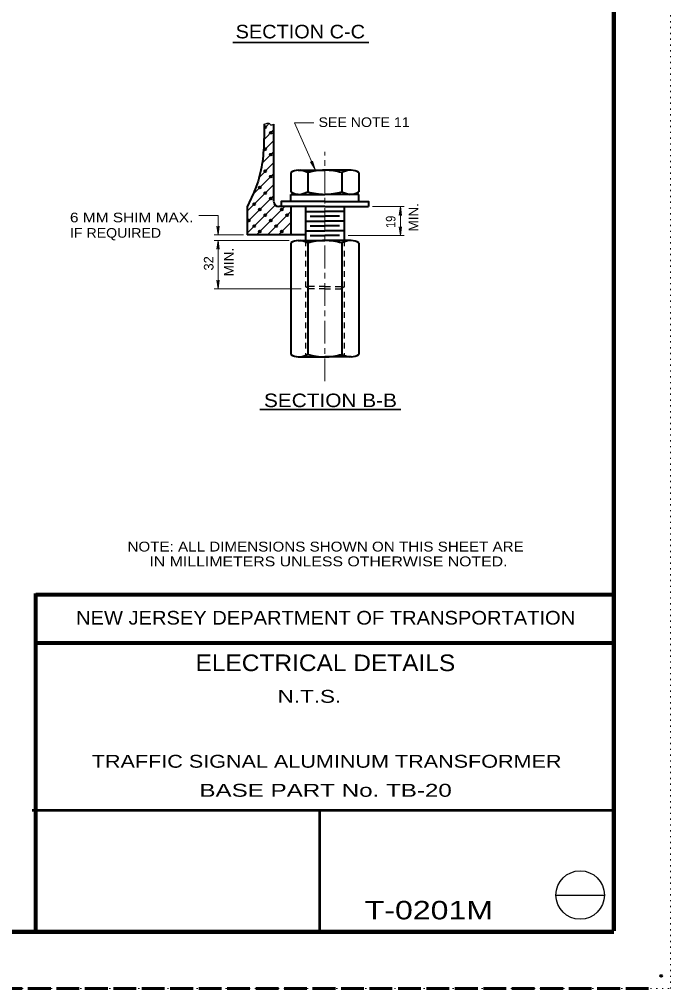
# Model space of a CAD drawing. Extents: x 312583 to 312854, y 144419 to 144597.
# Drawn here: x 312802 to 312853.5, y 144418.6 to 144495.2 of the extents above; entities that cross this region are included whole.
import ezdxf
from ezdxf.enums import TextEntityAlignment as Align

# ---------------------------------------------------------------- set-up
doc = ezdxf.new("R2010")
doc.units = 0
doc.header["$LTSCALE"] = 0.3
doc.header["$PDMODE"] = 32
doc.header["$PDSIZE"] = 0.15
for name, pattern in [('DOTTED', [1.5, 0.3, -1.2]), ('LONG_DASH_SHORT_DASH', [9.9, 6, -1.2, 1.5, -1.2]), ('LONG_DASHED', [7.5, 6, -1.5]), ('SHORT_DASHED', [2.7, 1.5, -1.2])]:
    doc.linetypes.add(name, pattern=pattern)
for name, color, linetype, lineweight in [('1', 7, 'Continuous', 40), ('2', 7, 'Continuous', 13), ('62', 7, 'DOTTED', 13), ('63', 7, 'LONG_DASHED', 60)]:
    doc.layers.add(name, color=color, linetype=linetype, lineweight=lineweight)
doc.layers.add('5', color=7, linetype='Continuous')

msp = doc.modelspace()

# ---------------------------------------------------------------- linework, layer by layer
at = {"layer": '1', "lineweight": 158}
for p, q in [((312849, 144423.1446), (312849, 144585.0846)), ((312616.5, 144423.0846), (312849, 144423.0846))]:
    msp.add_line(p, q, dxfattribs=at)
at = {"layer": '1', "lineweight": 13}
for p, q in [((312821.3437, 144485.6762), (312822.1411, 144486.4735)), ((312821.3667, 144486.5655), (312821.7117, 144486.9105)), ((312821.2977, 144484.7562), (312822.1411, 144485.5995)), ((312821.1904, 144483.7902), (312822.1411, 144484.7332)), ((312820.9681, 144482.6938), (312822.1411, 144483.8668)), ((312820.5541, 144481.4212), (312822.1411, 144483.0005)), ((312820.0327, 144480.0258), (312822.1411, 144482.1342)), ((312820.0327, 144479.1595), (312822.1411, 144481.2678)), ((312820.0327, 144478.2855), (312822.2254, 144480.4858)), ((312820.7687, 144478.1628), (312822.9997, 144480.3938)), ((312821.6351, 144478.1628), (312823.4827, 144480.0028)), ((312822.5014, 144478.1628), (312823.4827, 144479.1365)), ((312823.3754, 144478.1628), (312823.4827, 144478.2702))]:
    msp.add_line(p, q, dxfattribs=at)
at = {"layer": '1'}
for p, q in [((312822.1411, 144480.7772), (312822.1411, 144486.9105)), ((312823.4827, 144483.0772), (312823.4827, 144481.5438)), ((312824.0654, 144483.2688), (312826.1661, 144483.2688)), ((312824.8244, 144483.0772), (312824.8244, 144481.5438)), ((312828.2591, 144483.2688), (312826.1661, 144483.2688)), ((312827.5001, 144483.0772), (312827.5001, 144481.5438)), ((312828.8494, 144483.0772), (312828.8494, 144481.5438)), ((312823.4827, 144480.7772), (312823.4827, 144481.3522)), ((312823.4827, 144481.3522), (312826.1661, 144481.3522)), ((312828.8494, 144481.3522), (312826.1661, 144481.3522)), ((312828.8494, 144480.7772), (312828.8494, 144481.3522)), ((312820.0327, 144480.3938), (312820.0327, 144478.1628)), ((312822.7161, 144480.3938), (312822.5244, 144480.3938)), ((312826.1661, 144480.3938), (312822.7161, 144480.3938)), ((312823.4827, 144480.3938), (312823.4827, 144478.1628)), ((312824.6327, 144480.3938), (312824.6327, 144477.7105)), ((312826.1661, 144480.3938), (312829.6161, 144480.3938)), ((312827.6994, 144480.3938), (312827.6994, 144477.7105)), ((312824.6327, 144480.0105), (312826.1661, 144480.0105)), ((312825.0161, 144479.6272), (312826.1661, 144479.6272)), ((312827.6994, 144480.0105), (312826.1661, 144480.0105)), ((312827.3161, 144479.6272), (312826.1661, 144479.6272)), ((312824.6327, 144479.2438), (312826.1661, 144479.2438)), ((312825.0161, 144478.8605), (312826.1661, 144478.8605)), ((312827.6994, 144479.2438), (312826.1661, 144479.2438)), ((312827.3161, 144478.8605), (312826.1661, 144478.8605)), ((312824.6327, 144478.1628), (312820.0327, 144478.1628)), ((312824.6327, 144478.4772), (312826.1661, 144478.4772)), ((312825.0161, 144478.0938), (312826.1661, 144478.0938)), ((312827.6994, 144478.4772), (312826.1661, 144478.4772)), ((312827.3161, 144478.0938), (312826.1661, 144478.0938)), ((312823.4827, 144477.5188), (312823.4827, 144468.7022)), ((312824.0654, 144477.7105), (312826.1661, 144477.7105)), ((312824.8244, 144477.5188), (312824.8244, 144468.7022)), ((312828.2591, 144477.7105), (312826.1661, 144477.7105)), ((312827.5001, 144477.5188), (312827.5001, 144468.7022)), ((312828.8494, 144477.5188), (312828.8494, 144468.7022)), ((312824.0654, 144468.5105), (312826.1661, 144468.5105)), ((312828.2591, 144468.5105), (312826.1661, 144468.5105))]:
    msp.add_line(p, q, dxfattribs=at)
at = {"layer": '1', "linetype": 'LONG_DASH_SHORT_DASH', "lineweight": 13}
msp.add_line((312826.1661, 144466.5938), (312826.1661, 144484.7255), dxfattribs=at)
at = {"layer": '1', "linetype": 'SHORT_DASHED', "lineweight": 25}
for p, q in [((312824.6327, 144477.7105), (312824.6327, 144468.5105)), ((312827.6994, 144477.7105), (312827.6994, 144468.5105)), ((312826.1661, 144474.0688), (312824.6327, 144474.0688)), ((312824.9087, 144473.8772), (312824.6327, 144474.0688)), ((312826.1661, 144473.8772), (312824.9087, 144473.8772)), ((312826.1661, 144474.0688), (312827.6994, 144474.0688)), ((312826.1661, 144473.8772), (312827.4234, 144473.8772)), ((312827.4234, 144473.8772), (312827.6994, 144474.0688))]:
    msp.add_line(p, q, dxfattribs=at)
at = {"layer": '1', "lineweight": 80}
for p, q in [((312803.31, 144423.1446), (312803.31, 144449.8146)), ((312803.31, 144449.7246), (312849, 144449.7246)), ((312803.31, 144445.9146), (312849, 144445.9146))]:
    msp.add_line(p, q, dxfattribs=at)
at = {"layer": '1', "lineweight": 53}
for p, q in [((312849, 144432.6666), (312803.0383, 144432.6666)), ((312825.7547, 144432.6666), (312825.7547, 144423.1446))]:
    msp.add_line(p, q, dxfattribs=at)
at = {"layer": '1', "lineweight": 25}
msp.add_line((312844.4384, 144425.966), (312848.2794, 144425.966), dxfattribs=at)
at = {"layer": '1'}
for points in [[(312826.1661, 144480.7772), (312822.7161, 144480.7772), (312822.7161, 144480.3938)], [(312826.1661, 144480.7772), (312829.6161, 144480.7772), (312829.6161, 144480.3938)]]:
    msp.add_lwpolyline(points, dxfattribs=at)
at = {"layer": '1', "lineweight": 25}
msp.add_circle((312846.3494, 144425.9805), 1.9159, dxfattribs=at)
at = {"layer": '1'}
for centre, radius, start, end in [((312824.1006, 144482.1596), 1.1066, 91.66257, 124.1297), ((312823.5662, 144480.1666), 3.1689, 66.63635, 78.22986), ((312826.3032, 144477.5516), 5.7189, 91.405, 105.00202), ((312826.0228, 144477.5516), 5.7189, 74.99798, 88.595), ((312828.7598, 144480.1666), 3.1689, 101.77014, 113.36365), ((312828.2254, 144482.1596), 1.1066, 55.8703, 88.33743), ((312824.1006, 144482.4645), 1.1066, 235.8703, 268.33743), ((312823.5662, 144484.4575), 3.1689, 281.77014, 293.36365), ((312826.3032, 144487.0724), 5.7189, 254.99798, 268.595), ((312826.0228, 144487.0724), 5.7189, 271.405, 285.00202), ((312828.7598, 144484.4575), 3.1689, 246.63635, 258.22986), ((312828.2254, 144482.4645), 1.1066, 271.66257, 304.1297), ((312822.5229, 144480.7756), 0.3833, 180, 270), ((312824.1006, 144476.5997), 1.1066, 91.66257, 124.1297), ((312823.5662, 144474.6067), 3.1689, 66.63635, 78.22986), ((312826.3032, 144471.9918), 5.7189, 91.405, 105.00202), ((312826.0228, 144471.9918), 5.7189, 74.99798, 88.595), ((312828.7598, 144474.6067), 3.1689, 101.77014, 113.36365), ((312828.2254, 144476.5997), 1.1066, 55.8703, 88.33743), ((312824.1006, 144469.6182), 1.1066, 235.8703, 268.33743), ((312823.5662, 144471.6112), 3.1689, 281.77014, 293.36365), ((312826.3032, 144474.2262), 5.7189, 254.99798, 268.595), ((312826.0228, 144474.2262), 5.7189, 271.405, 285.00202), ((312828.7598, 144471.6112), 3.1689, 246.63635, 258.22986), ((312828.2254, 144469.6182), 1.1066, 271.66257, 304.1297)]:
    msp.add_arc(centre, radius, start, end, dxfattribs=at)
msp.add_spline([(312821.3744, 144486.9105), (312821.3514, 144485.5152), (312821.1981, 144483.7135), (312820.7381, 144481.9732), (312820.0327, 144480.3938)], degree=3, dxfattribs=at)
for p in [(312821.4587, 144486.6575), (312821.8957, 144486.2282), (312821.4587, 144484.9248), (312821.8957, 144484.4955), (312821.4587, 144483.1922), (312821.8957, 144482.7552), (312821.0294, 144481.8888), (312821.4587, 144481.4595), (312820.5924, 144480.5855), (312821.8957, 144481.0225), (312821.0294, 144480.1562), (312821.4587, 144479.7192), (312822.7621, 144480.1562), (312823.1914, 144479.7192), (312820.1554, 144479.2822), (312820.5924, 144478.8528), (312821.8957, 144479.2822), (312822.3251, 144478.8528), (312821.0294, 144478.4235), (312822.7621, 144478.4235), (312852.75, 144419.5846)]:
    msp.add_point(p, dxfattribs=at)
at = {"layer": '2', "lineweight": 35}
for p, q in [((312818.8934, 144493.3585), (312829.6468, 144493.3585)), ((312821.0371, 144464.3552), (312832.1691, 144464.3552))]:
    msp.add_line(p, q, dxfattribs=at)
at = {"layer": '2'}
for p, q in [((312825.0314, 144483.9205), (312825.2001, 144483.7518)), ((312825.3917, 144483.3148), (312825.0314, 144483.9205)), ((312825.1924, 144483.9895), (312825.2001, 144483.7518)), ((312825.3917, 144483.3148), (312825.1924, 144483.9895)), ((312832.4451, 144480.3938), (312829.9227, 144480.3938)), ((312832.1384, 144480.3938), (312832.0541, 144479.6962)), ((312832.1384, 144478.0938), (312832.1384, 144480.3938)), ((312832.1384, 144480.3938), (312832.2227, 144479.6962)), ((312816.1994, 144479.6962), (312817.7327, 144479.6962)), ((312817.7327, 144478.1628), (312817.7327, 144479.6962)), ((312832.0541, 144479.6962), (312832.1384, 144479.9185)), ((312832.2227, 144479.6962), (312832.1384, 144479.9185)), ((312817.6407, 144478.8528), (312817.7327, 144478.6305)), ((312817.7327, 144478.1628), (312817.6407, 144478.8528)), ((312817.8171, 144478.8528), (312817.7327, 144478.6305)), ((312817.7327, 144478.1628), (312817.8171, 144478.8528)), ((312819.7261, 144478.1628), (312817.4261, 144478.1628)), ((312832.4451, 144478.0938), (312827.9984, 144478.0938)), ((312832.0541, 144478.7838), (312832.1384, 144478.5615)), ((312832.1384, 144478.0938), (312832.0541, 144478.7838)), ((312832.2227, 144478.7838), (312832.1384, 144478.5615)), ((312832.1384, 144478.0938), (312832.2227, 144478.7838)), ((312823.3447, 144477.7105), (312817.4261, 144477.7105)), ((312817.7327, 144477.7105), (312817.6407, 144477.0128)), ((312817.7327, 144473.8772), (312817.7327, 144477.7105)), ((312817.7327, 144477.7105), (312817.8171, 144477.0128)), ((312817.6407, 144477.0128), (312817.7327, 144477.2352)), ((312817.8171, 144477.0128), (312817.7327, 144477.2352)), ((312817.6407, 144474.5672), (312817.7327, 144474.3448)), ((312817.7327, 144473.8772), (312817.6407, 144474.5672)), ((312817.8171, 144474.5672), (312817.7327, 144474.3448)), ((312817.7327, 144473.8772), (312817.8171, 144474.5672)), ((312824.2954, 144473.8772), (312817.4261, 144473.8772))]:
    msp.add_line(p, q, dxfattribs=at)
msp.add_lwpolyline([(312825.3917, 144483.3148), (312823.7587, 144487.0178), (312825.2921, 144487.0178)], dxfattribs=at)
at = {"layer": '2', "lineweight": 25}
msp.add_spline([(312821.3744, 144486.9105), (312821.5507, 144486.9642), (312821.7807, 144486.9642), (312821.8804, 144486.8568), (312822.1411, 144486.9105)], degree=3, dxfattribs=at)
at = {"layer": '62'}
msp.add_lwpolyline([(312601.2, 144418.5846), (312853.5, 144418.5846), (312853.5, 144596.7846)], dxfattribs=at)
at = {"layer": '63'}
msp.add_line((312851.75, 144418.5846), (312583.526, 144418.5846), dxfattribs=at)

# ---------------------------------------------------------------- texts
at = {"layer": '1'}
for s, width, p in [('NOTE: ALL DIMENSIONS SHOWN ON THIS SHEET ARE', 1.15, (312810.5642, 144453.1278)), ('     IN MILLIMETERS UNLESS OTHERWISE NOTED.', 1.2, (312810.5641, 144451.9578))]:
    msp.add_text(s, height=0.78, dxfattribs=dict(at, width=width)).set_placement(p)
at = {"layer": '1', "width": 1.1}
for s, height, p in [('NEW JERSEY DEPARTMENT OF TRANSPORTATION', 1.08, (312826.2285, 144447.3546)), ('ELECTRICAL DETAILS', 1.315, (312826.2109, 144443.6759))]:
    msp.add_text(s, height=height, dxfattribs=at).set_placement(p, align=Align.CENTER)
at = {"layer": '2'}
for s, height, width, p in [('SECTION C-C', 1.07, 1.1, (312824.2285, 144493.6826)), ('SECTION B-B', 1.07, 1.15, (312826.6107, 144464.539)), ('     N.T.S. ', 1.02, 1.3, (312823.9633, 144441.1717)), ('     TRAFFIC SIGNAL ALUMINUM TRANSFORMER    ', 1.02, 1.25, (312826.0728, 144436.0399)), ('             BASE PART No. TB-20            ', 1.02, 1.4, (312825.9617, 144433.7476))]:
    msp.add_text(s, height=height, dxfattribs=dict(at, width=width)).set_placement(p, align=Align.CENTER)
for s, width, p in [('SEE NOTE 11', 1.1, (312825.6688, 144486.6788)), ('6 MM SHIM MAX.', 1.2, (312806.0191, 144479.1483)), ('IF REQUIRED', 1.1, (312806.0191, 144477.9283))]:
    msp.add_text(s, height=0.76, dxfattribs=dict(at, width=width)).set_placement(p)
for s, width, p in [('MIN.', 1.05, (312833.5574, 144478.42)), ('19', 0.85, (312831.7503, 144478.7037)), ('MIN.', 1.05, (312818.9586, 144474.8739))]:
    msp.add_text(s, height=0.76, rotation=90, dxfattribs=dict(at, width=width)).set_placement(p)
msp.add_text('32', height=0.76, rotation=90, dxfattribs=at).set_placement((312817.3641, 144475.3349))
at = {"layer": '5', "width": 1.3}
msp.add_text('T-0201M  ', height=1.457, dxfattribs=at).set_placement((312835.0922, 144424.0569), align=Align.CENTER)

doc.saveas('drawing.dxf')
